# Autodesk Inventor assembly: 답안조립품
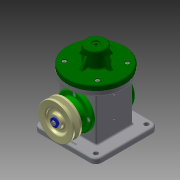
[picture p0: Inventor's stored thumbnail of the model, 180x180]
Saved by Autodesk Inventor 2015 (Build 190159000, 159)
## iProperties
Created: 2021-05
Part Number: 답안조립품
Document SubType Name: Assembly
Designer: 101654789
Author: 101654789
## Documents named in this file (19)
- C:\Users\101654789\Desktop\710506V1005\답안조립품.iam
- C:\Users\101654789\Desktop\710506V1005\E-링.ipt
- C:\Users\101654789\Desktop\710506V1005\V-벨트풀리.ipt
- C:\Users\101654789\Desktop\710506V1005\덮개.ipt
- C:\Users\101654789\Desktop\710506V1005\뒤커버.ipt
- C:\Users\101654789\Desktop\710506V1005\링크.ipt
- C:\Users\101654789\Desktop\710506V1005\베어링 17 x 40 x 12.ipt
- C:\Users\101654789\Desktop\710506V1005\본체.ipt
- C:\Users\101654789\Desktop\710506V1005\볼트 M4 x 10.ipt
- C:\Users\101654789\Desktop\710506V1005\볼트 M4 x 12.ipt
- 볼트 M4 x 12.ipt
- C:\Users\101654789\Desktop\710506V1005\슬라이더.ipt
- C:\Users\101654789\Desktop\710506V1005\앞커버.ipt
- C:\Users\101654789\Desktop\710506V1005\오일 실 17 30 8.ipt
- C:\Users\101654789\Desktop\710506V1005\와셔 4x16.ipt
- C:\Users\101654789\Desktop\710506V1005\클레비스 핀 6 x 22.ipt
- 클레비스 핀 6 x 22.ipt
- C:\Users\101654789\Desktop\710506V1005\키 4 x 4 x 12.ipt
- C:\Users\101654789\Desktop\710506V1005\편심축.ipt
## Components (2 placed, 2 different names)
1. E-링:1
2. V-벨트풀리:1
